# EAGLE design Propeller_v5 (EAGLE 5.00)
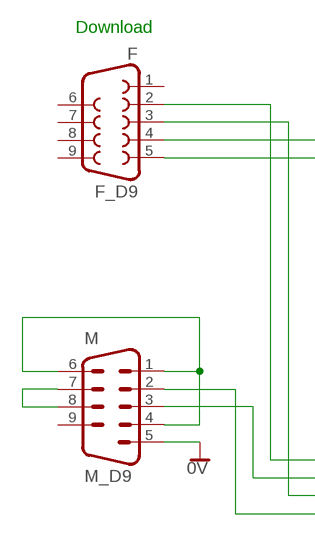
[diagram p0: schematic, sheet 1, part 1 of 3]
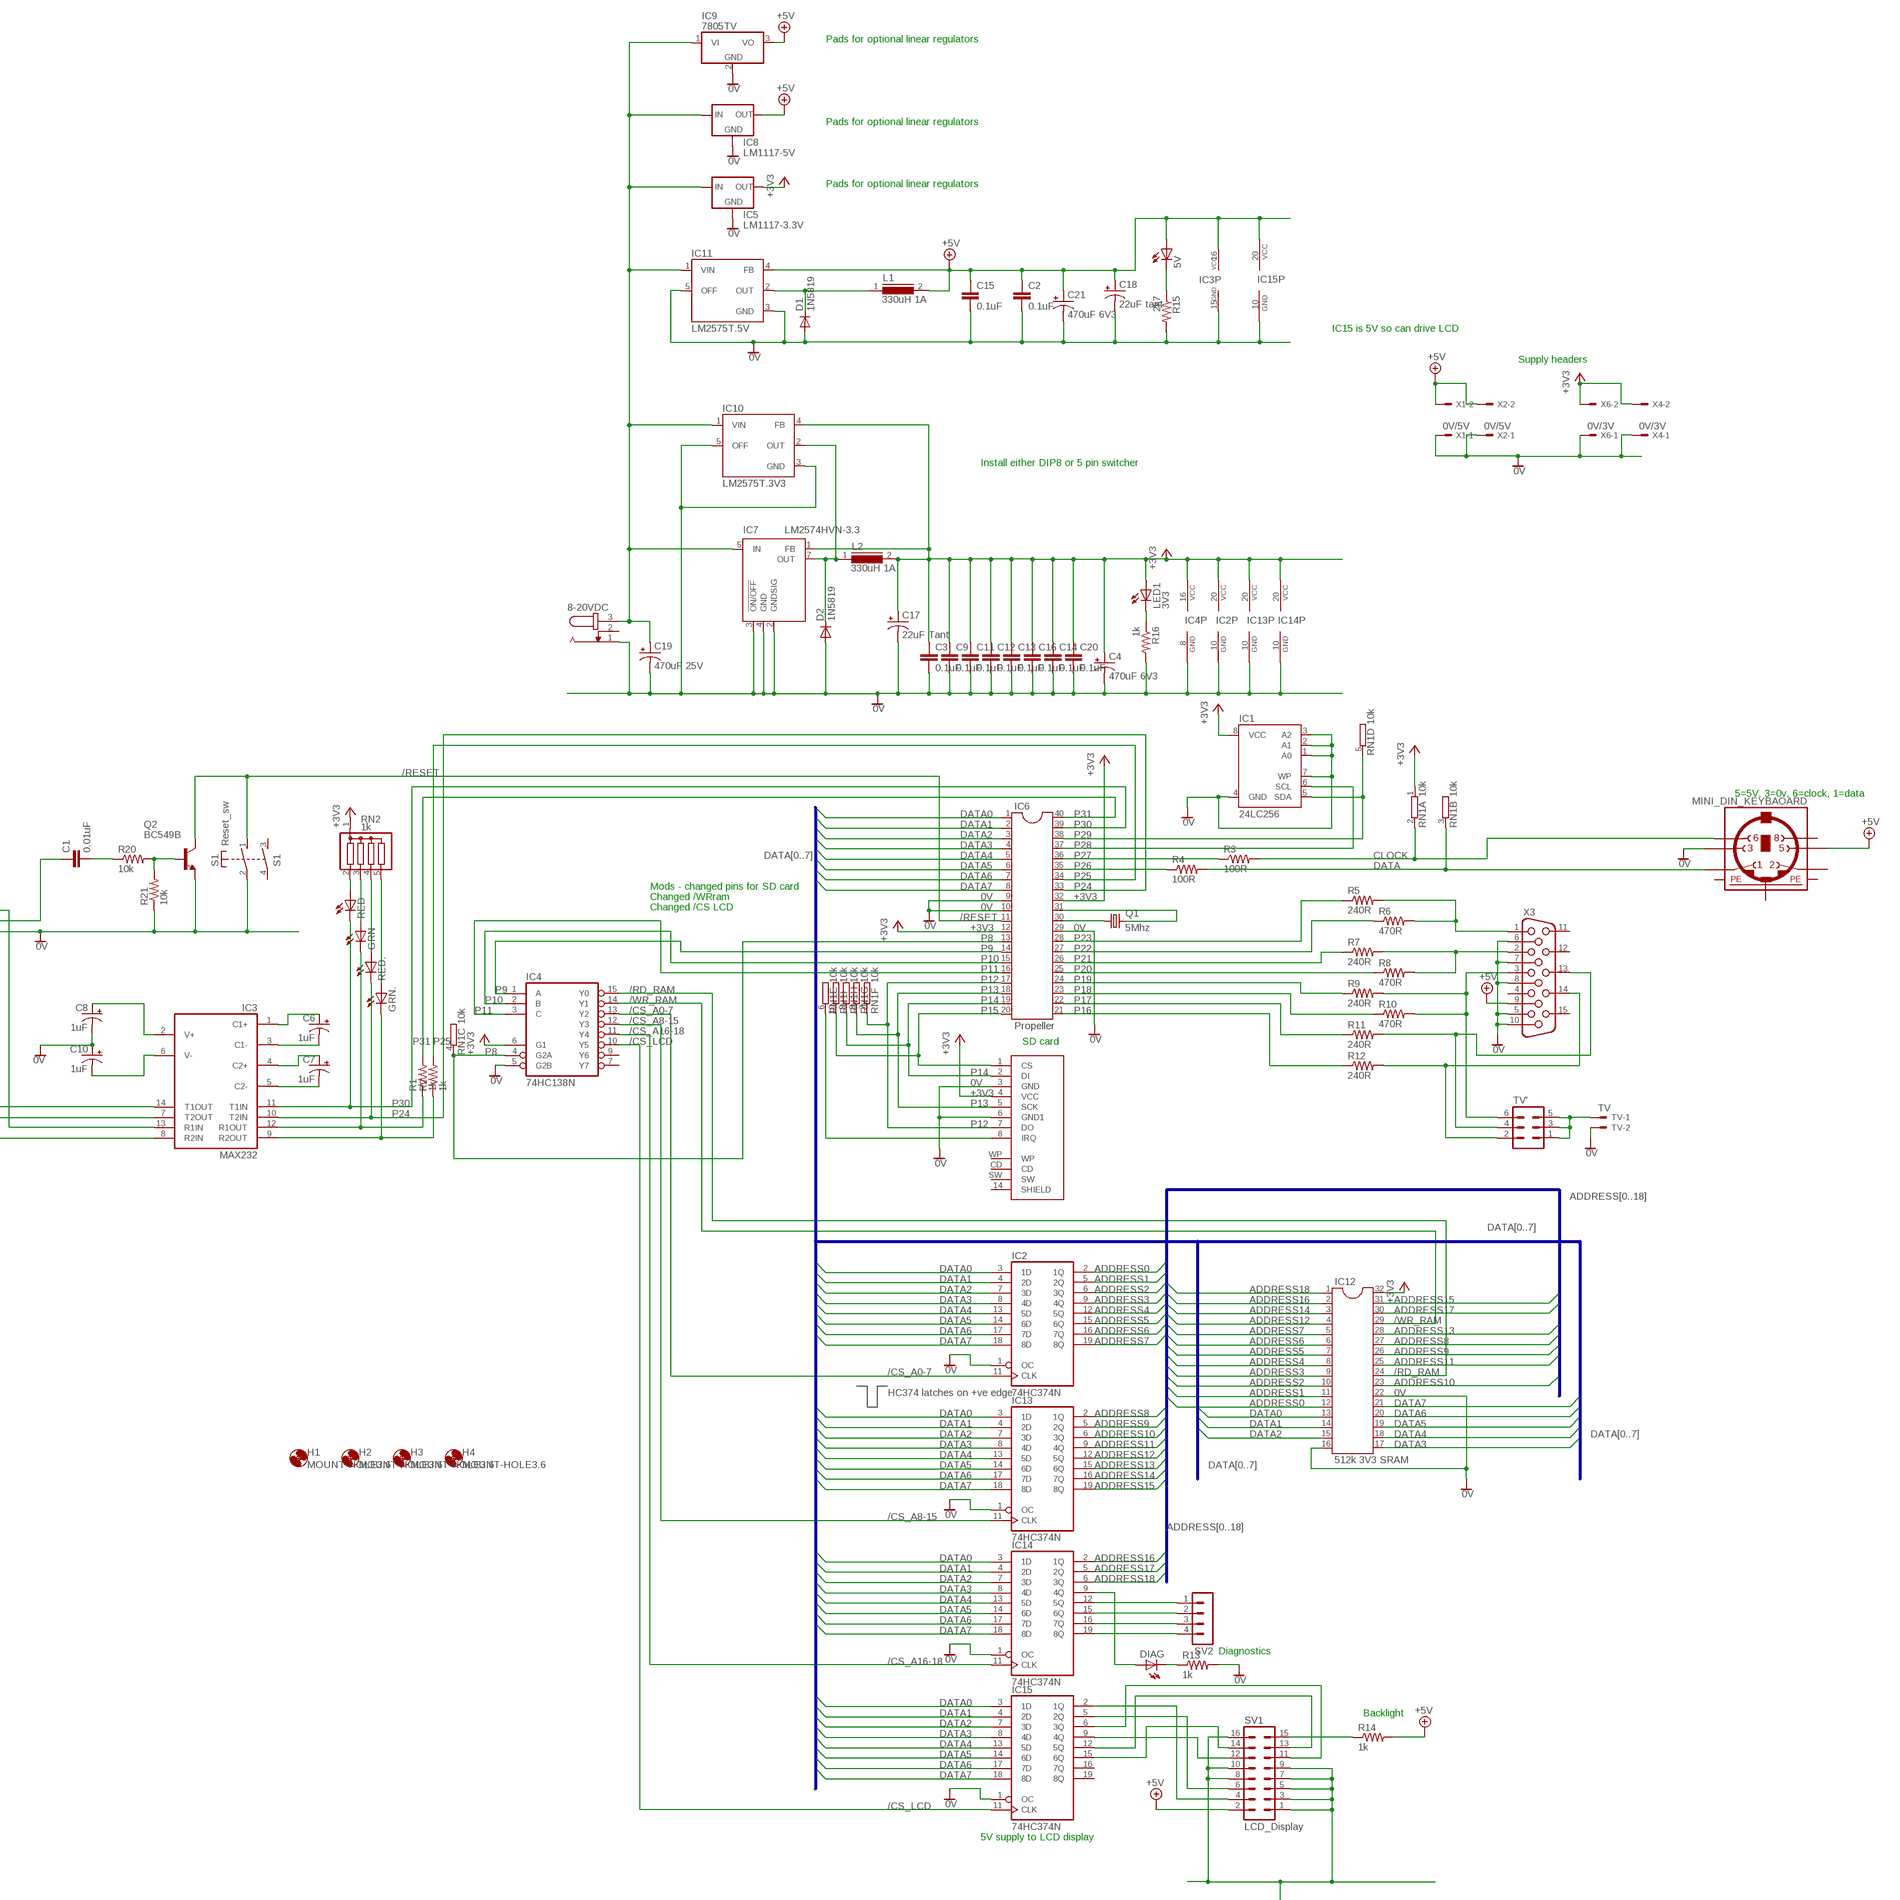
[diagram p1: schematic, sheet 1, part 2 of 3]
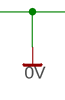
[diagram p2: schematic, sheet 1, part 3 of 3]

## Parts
5V  LED5MM  [LED5MM]
8-20VDC  JACK-PLUG0  [SPC4077]
C1  0.01uF  C-EU025-024X044  [C025-024X044]
C2  0.1uF  C-EU050-024X044  [C050-024X044]
C3  0.1uF  C-EU050-024X044  [C050-024X044]
C4  470uF 6V3  CPOL-USE5-8.5  [E5-8,5]
C6  1uF  CPOL-USE5-5  [E5-5]
C7  1uF  CPOL-USE5-5  [E5-5]
C8  1uF  CPOL-USE5-5  [E5-5]
C9  0.1uF  C-EU050-024X044  [C050-024X044]
C10  1uF  CPOL-USE5-5  [E5-5]
C11  0.1uF  C-EU050-024X044  [C050-024X044]
C12  0.1uF  C-EU050-024X044  [C050-024X044]
C13  0.1uF  C-EU050-024X044  [C050-024X044]
C14  0.1uF  C-EU050-024X044  [C050-024X044]
C15  0.1uF  C-EU050-024X044  [C050-024X044]
C16  0.1uF  C-EU050-024X044  [C050-024X044]
C17  22uF Tant  CPOL-USE5-5  [E5-5]
C18  22uF tant  CPOL-USE5-5  [E5-5]
C19  470uF 25V  CPOL-USE5-10.5  [E5-10,5]
C20  0.1uF  C-EU050-024X044  [C050-024X044]
C21  470uF 6V3  CPOL-USE5-8.5  [E5-8,5]
D1  1N5819  1N4004  [DO41-10]
D2  1N5819  1N4004  [DO41-10]
DIAG  LED5MM  [LED5MM]
F  F_D9  F09HP  [F09HP]
GRN  LED3MM  [LED3MM]
GRN.  LED3MM  [LED3MM]
H1  MOUNT-HOLE3.6  [3,6]
H2  MOUNT-HOLE3.6  [3,6]
H3  MOUNT-HOLE3.6  [3,6]
H4  MOUNT-HOLE3.6  [3,6]
IC1  24LC256  AT24CP  [DIL08]
IC2  74HC374N  74LS374N  [DIL20]
IC3  MAX232  [DIL16]
IC4  74HC138N  74LS138N  [DIL16]
IC5  LM1117-3.3V  LM1117V  [78XXS]
IC6  Propeller  DIL40  [DIL40]
IC7  LM2574HVN-3.3  [DIL08]
IC8  LM1117-5V  LM1117V  [78XXS]
IC9  7805TV  [TO220V]
IC10  LM2575T.3V3  LM2575T  [TO220-5]
IC11  LM2575T.5V  LM2575T  [TO220-5]
IC12  512k 3V3 SRAM  DIL32  [DIL32]
IC13  74HC374N  74LS374N  [DIL20]
IC14  74HC374N  74LS374N  [DIL20]
IC15  74HC374N  74LS374N  [DIL20]
L1  330uH 1A  82114R  [82114R]
L2  330uH 1A  82114R  [82114R]
LED1  3V3  LED5MM  [LED5MM]
M  M_D9  M09HP  [M09HP]
MINI_DIN_KEYBAOARD  MINI_DIN_6  [M_DIN6]
Q1  5Mhz  CRYSTALHC18U-V  [HC18U-V]
Q2  BC549B  [TO92-EBC]
R1  1k  R-US_0207/10  [0207/10]
R2  1k  R-US_0207/10  [0207/10]
R3  100R  R-US_0207/10  [0207/10]
R4  100R  R-US_0207/10  [0207/10]
R5  240R  R-US_0207/10  [0207/10]
R6  470R  R-US_0207/10  [0207/10]
R7  240R  R-US_0207/10  [0207/10]
R8  470R  R-US_0207/10  [0207/10]
R9  240R  R-US_0207/10  [0207/10]
R10  470R  R-US_0207/10  [0207/10]
R11  240R  R-US_0207/10  [0207/10]
R12  240R  R-US_0207/10  [0207/10]
R13  1k  R-US_0207/10  [0207/10]
R14  1k  R-US_0207/10  [0207/10]
R15  2k7  R-US_0207/10  [0207/10]
R16  1k  R-US_0207/10  [0207/10]
R20  10k  R-US_0207/10  [0207/10]
R21  10k  R-US_0207/10  [0207/10]
RED  LED3MM  [LED3MM]
RED.  LED3MM  [LED3MM]
RN1  10k  GE09R  [SIL10]
RN2  1k  G04R  [SIL5]
S1  Reset_sw  PVA1F  [PVA1F]
SV1  LCD_Display  MA08-2  [MA08-2]
SV2  MA04-1  [MA04-1]
TV  TV  22-23-2021  [22-23-2021]
TV'  MA03-2  [MA03-2]
U$1  SD_CARD_SOCKETSD  [SD-MMC_SOCKET-PP]
X1  0V/5V  22-23-2021  [22-23-2021]
X2  0V/5V  22-23-2021  [22-23-2021]
X3  HF15H  [HDF15H]
X4  0V/3V  22-23-2021  [22-23-2021]
X6  0V/3V  22-23-2021  [22-23-2021]

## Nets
0V [Gnd]: 8-20VDC.1 C2.2 C3.2 C4.- C8.- C9.2 C10.+ C11.2 C12.2 C13.2 C14.2 C15.2 C16.2 C17.- C18.- C19.- C20.2 C21.- D1.A D2.A F.5 IC1.1(A0) IC1.2(A1) IC1.3(A2) IC1.4(GND) IC1.7(WP) IC2.1(OC) IC2.10(GND) IC3.15(GND) IC4.5(G2B) IC4.8(GND) IC5.IN(GND) IC6.9 IC6.10 IC6.29 IC7.2(GNDSIG) IC7.3(!ON/OFF) IC7.4(GND) IC8.IN(GND) IC9.2(GND) IC10.3(GND) IC10.5(OFF) IC11.3(GND) IC11.5(OFF) IC12.16 IC12.22 IC13.1(OC) IC13.10(GND) IC14.1(OC) IC14.10(GND) IC15.1(OC) IC15.10(GND) M.5 MINI_DIN_KEYBAOARD.3 Q2.E R13.2 R15.2 R16.2 R21.1 S1.2(1:P) SV1.1 SV1.3 SV1.5 SV1.7 SV1.8 SV1.9 SV1.10 SV1.16 TV.2 U$1.3(GND) U$1.6(GND1) X1.1 X2.1 X3.5 X3.6 X3.7 X3.8 X3.10 X4.1 X6.1
+3V3 [3V]: C3.1 C4.+ C9.1 C11.1 C12.1 C13.1 C14.1 C16.1 C17.+ C20.1 IC1.8(VCC) IC2.20(VCC) IC4.6(G1) IC4.16(VCC) IC5.GND(OUT) IC6.12 IC6.32 IC7.1(FB) IC10.4(FB) IC12.32 IC13.20(VCC) IC14.20(VCC) L2.2 LED1.A RN1.1 RN2.1 U$1.4(VCC) X4.2 X6.2
+5V [5V]: 5V.A C2.1 C15.1 C18.+ C21.+ IC3.16(VCC) IC8.GND(OUT) IC9.3(VO) IC11.4(FB) IC15.20(VCC) L1.2 MINI_DIN_KEYBAOARD.5 R14.2 SV1.2 X1.2 X2.2 X3.9
/CS_A0-7: IC2.11(CLK) IC4.13(Y2)
/CS_A8-15: IC4.12(Y3) IC13.11(CLK)
/CS_A16-18: IC4.11(Y4) IC14.11(CLK)
/CS_LCD: IC4.10(Y5) IC15.11(CLK)
/RD_RAM: IC4.15(Y0) IC12.24
/RESET: IC6.11 Q2.C S1.1(1:S)
/WR_RAM: IC4.14(Y1) IC12.29
ADDRESS0: IC2.2(1Q) IC12.12
ADDRESS1: IC2.5(2Q) IC12.11
ADDRESS2: IC2.6(3Q) IC12.10
ADDRESS3: IC2.9(4Q) IC12.9
ADDRESS4: IC2.12(5Q) IC12.8
ADDRESS5: IC2.15(6Q) IC12.7
ADDRESS6: IC2.16(7Q) IC12.6
ADDRESS7: IC2.19(8Q) IC12.5
ADDRESS8: IC12.27 IC13.2(1Q)
ADDRESS9: IC12.26 IC13.5(2Q)
ADDRESS10: IC12.23 IC13.6(3Q)
ADDRESS11: IC12.25 IC13.9(4Q)
ADDRESS12: IC12.4 IC13.12(5Q)
ADDRESS13: IC12.28 IC13.15(6Q)
ADDRESS14: IC12.3 IC13.16(7Q)
ADDRESS15: IC12.31 IC13.19(8Q)
ADDRESS16: IC12.2 IC14.2(1Q)
ADDRESS17: IC12.30 IC14.5(2Q)
ADDRESS18: IC12.1 IC14.6(3Q)
CLOCK: MINI_DIN_KEYBAOARD.6 R3.2 RN1.2
DATA: MINI_DIN_KEYBAOARD.1 R4.2 RN1.3
DATA0: IC2.3(1D) IC6.1 IC12.13 IC13.3(1D) IC14.3(1D) IC15.3(1D)
DATA1: IC2.4(2D) IC6.2 IC12.14 IC13.4(2D) IC14.4(2D) IC15.4(2D)
DATA2: IC2.7(3D) IC6.3 IC12.15 IC13.7(3D) IC14.7(3D) IC15.7(3D)
DATA3: IC2.8(4D) IC6.4 IC12.17 IC13.8(4D) IC14.8(4D) IC15.8(4D)
DATA4: IC2.13(5D) IC6.5 IC12.18 IC13.13(5D) IC14.13(5D) IC15.13(5D)
DATA5: IC2.14(6D) IC6.6 IC12.19 IC13.14(6D) IC14.14(6D) IC15.14(6D)
DATA6: IC2.17(7D) IC6.7 IC12.20 IC13.17(7D) IC14.17(7D) IC15.17(7D)
DATA7: IC2.18(8D) IC6.8 IC12.21 IC13.18(8D) IC14.18(8D) IC15.18(8D)
N$1 [Fat]: 8-20VDC.3 C19.+ IC5.OUT(IN) IC7.5(IN) IC8.OUT(IN) IC9.1(VI) IC10.1(VIN) IC11.1(VIN)
N$2: GRN.K(C) IC3.12(R1OUT) R1.1
N$3: TV'.1 TV'.3 TV'.5 TV.1
N$4: IC6.30 Q1.1
N$5: DIAG.A IC14.9(4Q)
N$6: F.3 IC3.13(R1IN)
N$7: C1.1 F.4
N$8: Q2.B R20.2 R21.2
N$9: C1.2 R20.1
N$10: IC14.12(5Q) SV2.1
N$11: IC14.15(6Q) SV2.2
N$12: IC6.31 Q1.2
N$13: IC14.16(7Q) SV2.3
N$14: IC14.19(8Q) SV2.4
N$15: DIAG.K(C) R13.1
N$16 [Fat]: D1.C IC11.2(OUT) L1.1
N$17: R14.1 SV1.15
N$18: GRN..K(C) IC3.9(R2OUT) R2.1
N$19: R5.2 R6.2 X3.1
N$20: IC15.2(1Q) SV1.4
N$21: R7.2 R8.2 X3.2
N$22: IC15.5(2Q) SV1.6
N$23: IC15.6(3Q) SV1.11
N$24: IC15.9(4Q) SV1.12
N$25: R9.2 R10.2 TV'.6 X3.3
N$26: IC15.12(5Q) SV1.13
N$27: IC15.15(6Q) SV1.14
N$28: R11.2 TV'.4 X3.13
N$29: F.2 IC3.14(T1OUT)
N$30: R12.2 TV'.2 X3.14
N$32: 5V.K(C) R15.1
N$34: RED.A RN2.2
N$35 [Fat]: D2.C IC7.7(OUT) IC10.2(OUT) L2.1
N$36: C6.+ IC3.1(C1+)
N$37: C6.- IC3.3(C1-)
N$38: C7.+ IC3.4(C2+)
N$39: C7.- IC3.5(C2-)
N$40: C8.+ IC3.2(V+)
N$41: C10.- IC3.6(V-)
N$42: LED1.K(C) R16.1
N$43: GRN.A RN2.3
N$44: RED..A RN2.4
N$45: GRN..A RN2.5
N$46: RN1.6 U$1.8(IRQ)
N$49: M.1 M.4 M.6
N$51: M.7 M.8
N$57: IC3.7(T2OUT) M.3
N$61: IC3.8(R2IN) M.2
P8 [3V]: IC4.4(G2A) IC6.13 RN1.4
P9: IC4.1(A) IC6.14
P10: IC4.2(B) IC6.15
P11: IC4.3(C) IC6.16
P12: IC6.17 RN1.7 U$1.7(DO)
P13: IC6.18 RN1.8 U$1.5(SCK)
P14: IC6.19 RN1.9 U$1.2(DI)
P15: IC6.20 RN1.10 U$1.1(CS)
P16: IC6.21 R12.1
P17: IC6.22 R11.1
P18: IC6.23 R10.1
P19: IC6.24 R9.1
P20: IC6.25 R8.1
P21: IC6.26 R7.1
P22: IC6.27 R6.1
P23: IC6.28 R5.1
P24: IC3.10(T2IN) IC6.33 RED..K(C)
P25: IC6.34 R2.2
P26: IC6.35 R4.1
P27: IC6.36 R3.1
P28: IC1.6(SCL) IC6.37
P29: IC1.5(SDA) IC6.38 RN1.5
P30: IC3.11(T1IN) IC6.39 RED.K(C)
P31: IC6.40 R1.2
Unconnected: 8-20VDC.2 F.1 F.6 F.7 F.8 F.9 IC4.7(Y7) IC4.9(Y6) IC15.16(7Q) IC15.19(8Q) M.9 MINI_DIN_KEYBAOARD.2 MINI_DIN_KEYBAOARD.8 S1.3(2:S) S1.4(2:P) U$1.14(SHIELD) U$1.CD U$1.SW U$1.WP X3.4 X3.11 X3.12 X3.15

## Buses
DATA[0..7]
ADDRESS[0..18]

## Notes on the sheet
- Pads for optional linear regulators
- Pads for optional linear regulators
- Pads for optional linear regulators
- IC15 is 5V so can drive LCD
- Supply headers
- Install either DIP8 or 5 pin switcher
- 5=5V, 3=0v, 6=clock, 1=data
- Download
- Mods - changed pins for SD card
- Changed /WRram
- Changed /CS LCD
- SD card
- HC374 latches on +ve edge
- Diagnostics
- Backlight
- 5V supply to LCD display

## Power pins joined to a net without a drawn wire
PE1: MINI_DIN_KEYBAOARD.SH1(PE1)
PE2: MINI_DIN_KEYBAOARD.SH2(PE2)
PE3: MINI_DIN_KEYBAOARD.SH3(PE3)

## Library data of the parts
5V DIAG GRN GRN. LED1 RED RED. = led:LED: LED
8-20VDC = con-jack:JACK-PLUG: DC POWER JACK Power Jack, DC, Right Angle, Through Hole, Rated 5A at 16VDC, PC Terminals Distributor: Farnell (www.Farnell.de) Drawing: 84N1161.pdf / 84N1162.pdf Manufacturer: SPC Technology (www.spctechnology.com) Type: SPC4077 / SPC 4078
C1-C3 C9 C11-C16 C20 = rcl:C-EU: CAPACITOR, European symbol
C4 C6-C8 C10 C17-C19 C21 = rcl:CPOL-US: POLARIZED CAPACITOR, American symbol
D1 D2 = diode:1N4004: DIODE
F = con-subd:F09: SUB-D
H1-H4 = holes:MOUNT-HOLE: MOUNTING HOLE with drill center marker
IC1 = atmel:AT24C*: 2-wire serial EEPROM
IC2 IC13-IC15 = 74xx-us:74*374: Octal D type transparent LATCH, edge triggered
IC3 = maxim:MAX232: RS232 TRANSEIVER
IC4 = 74xx-us:74*138: 3-line to 8-line DECODER/DEMULTIPLEXER
IC5 IC8 = v-reg-3:LM1117
IC6 = ic-package:DIL40: Dual In Line
IC7 = linear:LM2574?-*: SIMPLE SWITCHER 0.5A Step-Down Voltage Regulator Source: http://cache.national.com/ds/LM/LM2574.pdf
IC9 = linear:78*: Positive VOLTAGE REGULATOR Source: http://cache.national.com/ds/LM/LM78L05.pdf http://www.fairchildsemi.com/ds/LM/LM7805.pdf
IC10 IC11 = v-reg-3:LM2575: National Semiconductor 1.0A "Simple Switcher"(c) 52kHz, Vout 1.23-37V (HV: 57V), Vin 40V (HV: 60V), 50µA standby current
IC12 = ic-package:DIL32: Dual In Line
L1 L2 = inductors:82114R: INDUCTOR
M = con-subd:M09: SUB-D
MINI_DIN_KEYBAOARD = mini_din:MINI_DIN_6
Q1 = crystal:CRYSTAL: CRYSTAL
Q2 = transistor-npn:BC549*: NPN Transistor
R1-R16 R20 R21 = rcl:R-US_: RESISTOR, American symbol
RN1 = resistor-sil:GE09R: SIL RESISTOR
RN2 = resistor-sil:G04R: SIL RESISTOR
S1 = switch-misc:PVA1: ITT SWITCH
SV1 = con-lstb:MA08-2: PIN HEADER
SV2 = con-lstb:MA04-1: PIN HEADER
TV X1 X2 X4 X6 = con-molex:22-23-2021: .100" (2.54mm) Center Header - 2 Pin
TV' = con-lstb:MA03-2: PIN HEADER
U$1 = SparkFunEagle-6-6-07:SD_CARD_SOCKET: SD/MMC Socket Media socket for SD and MMC cards. Push-push type. Schematic element and footprint production proven. Spark Fun Electronics SKU : PRT-00136
X3 = con-subd:HF15: SUB-D

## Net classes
1 5V: width 0.635 mm
2 3V: width 0.762 mm
3 Gnd: width 0.762 mm
4 Fat: width 1.27 mm

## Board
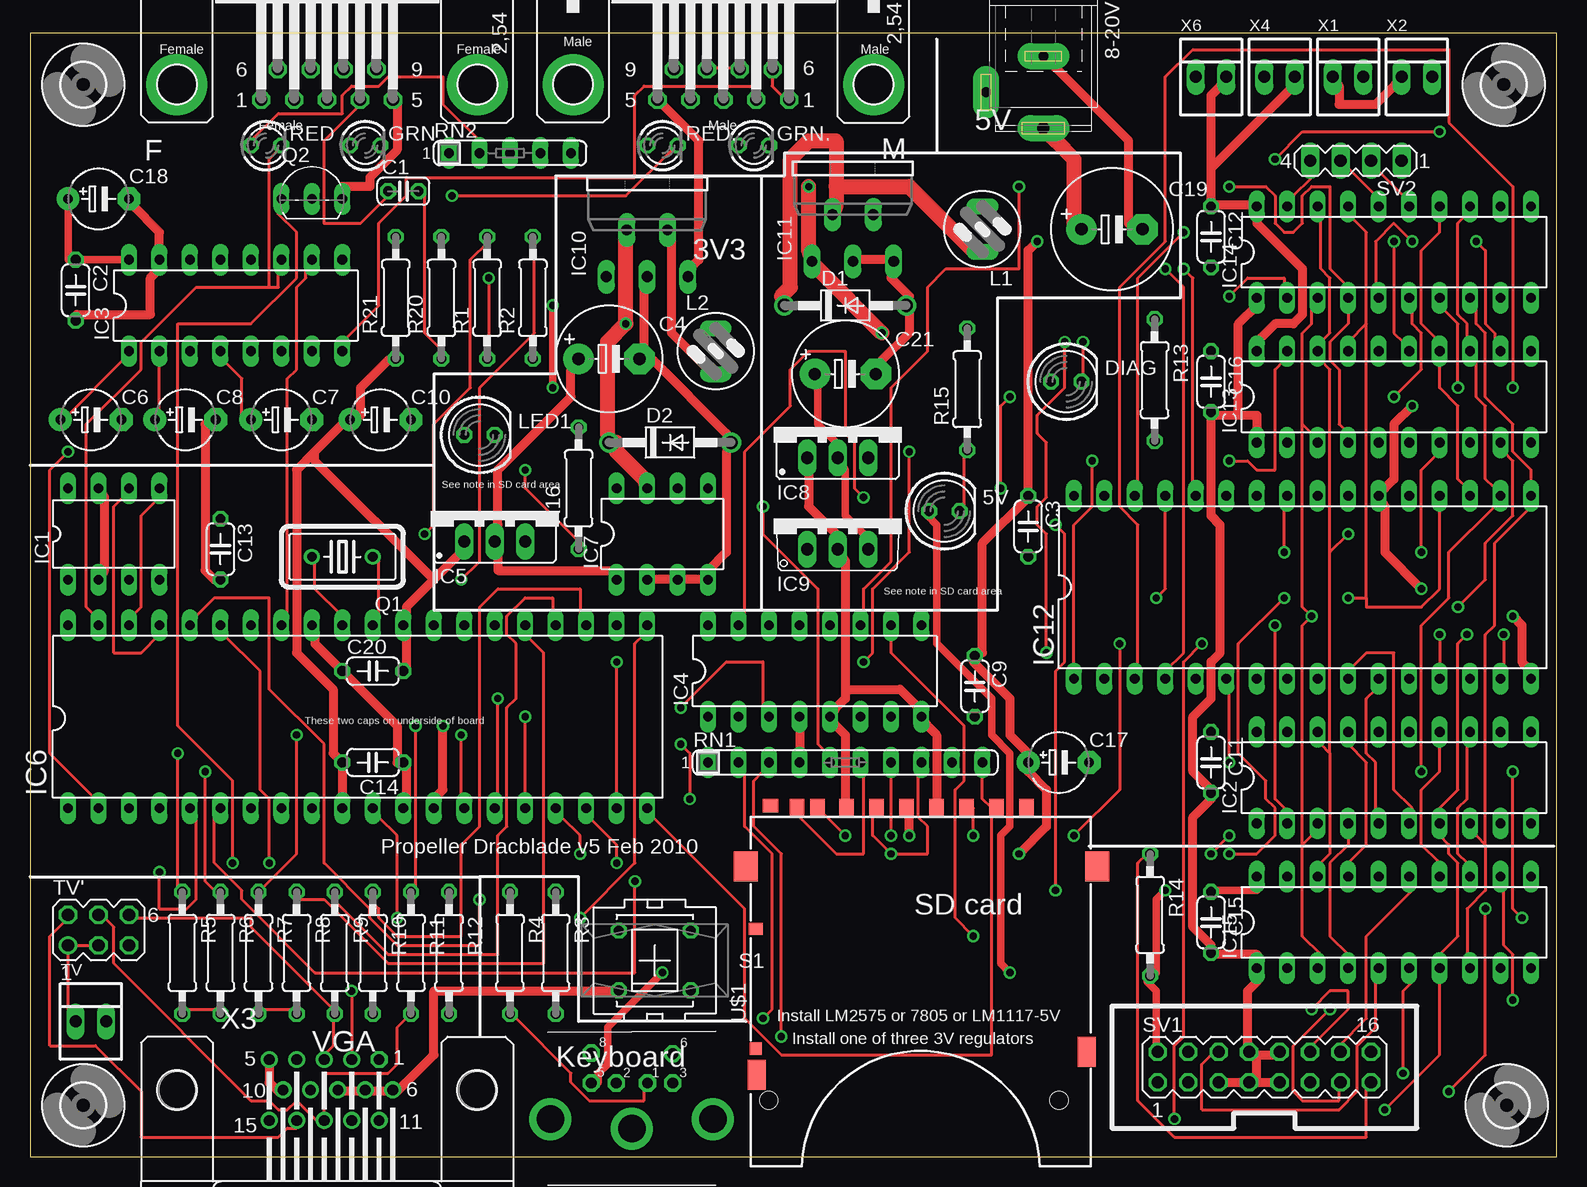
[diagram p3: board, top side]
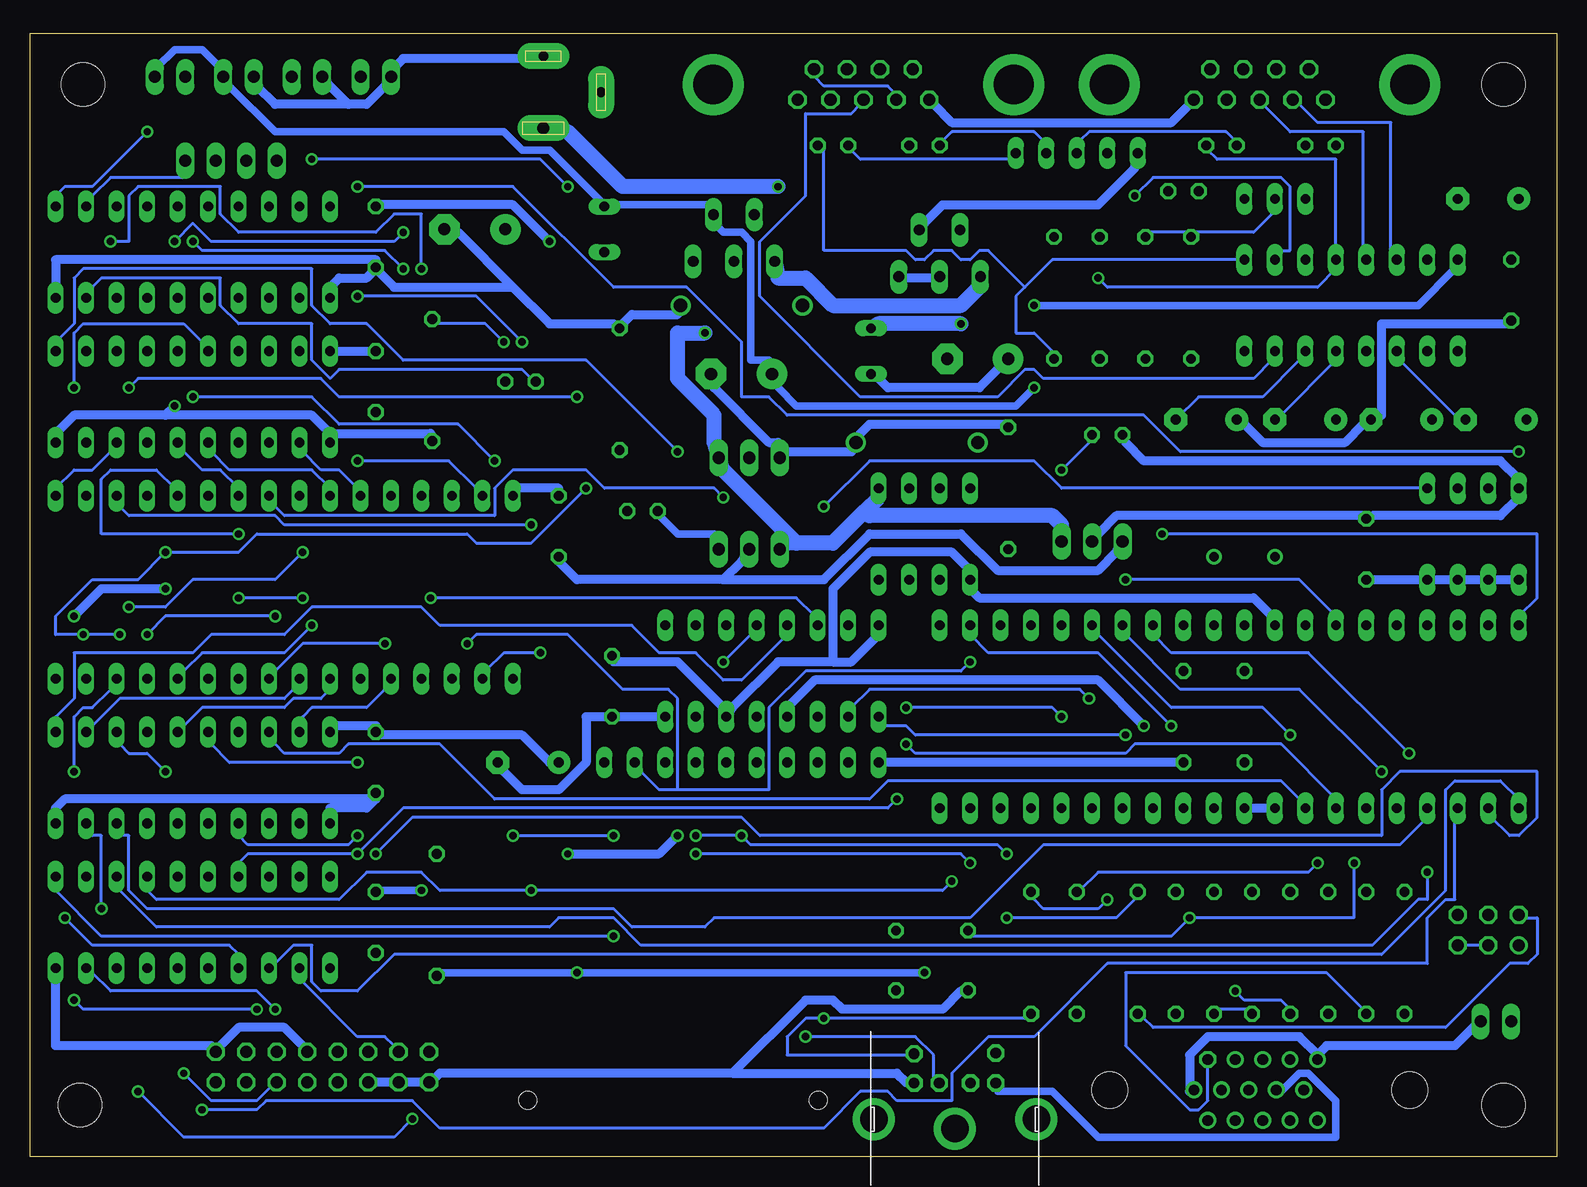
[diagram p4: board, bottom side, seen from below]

Size 127.23 x 93.65 mm. Coordinates in mm from the lower left corner, seen from the top.
Outline: 0,0 127.23,0 127.23,93.65 0,93.65 0,0
Copper layers (1*16): Top 0.035mm / dielectric 1.5mm / Bottom 0.035mm
Design rules "default *": minimum track width 10mil, minimum drill 24mil, track to track 8mil, track to pad 8mil, pad to pad 8mil, via to via 8mil, smd to smd 8mil, copper to edge 40mil, drill to drill 8mil, minimum pad ring 10mil, minimum via ring 8mil, stop-mask expansion 4mil, vias tented up to drill 0mil, thermal gap 10mil

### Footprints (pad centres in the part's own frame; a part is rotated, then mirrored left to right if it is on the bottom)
LED5MM = drill 0.813 octagon: A -1.27,0; K 1.27,0
SPC4077 = drill 0.8 pad 2.184 long: 1 -3,0; 2 0,-4.8 | drill 1 pad 2.184 long: 3 3,0
C025-024X044 = drill 0.813 octagon: 1 -1.27,0; 2 1.27,0
C050-024X044 = drill 0.813 octagon: 1 -2.54,0; 2 2.54,0
E5-8,5 = drill 1.016 pad 2.54 round: + -2.54,0 | drill 1.016 pad 2.54 octagon: - 2.54,0
E5-5 = drill 0.813 pad 1.905 round: + -2.54,0 | drill 0.813 pad 1.905 octagon: - 2.54,0
E5-10,5 = drill 1.016 pad 2.54 round: + -2.54,0 | drill 1.016 pad 2.54 octagon: - 2.54,0
DO41-10 = drill 1.118 round: A 5.08,0; C -5.08,0
F09HP = drill 1.016 octagon: 1 -5.486,-1.27; 2 -2.743,-1.27; 3 0,-1.27; 4 2.743,-1.27; 5 5.486,-1.27; 6 -4.115,1.27; 7 -1.372,1.27; 8 1.372,1.27; 9 4.115,1.27 | drill 3.302 pad 5.08 round: G1 -12.522,0; G2 12.522,0
LED3MM = drill 0.813 octagon: A -1.27,0; K 1.27,0
3,6 = hole 3.6: 0,0
DIL08 = drill 0.813 long: 1 -3.81,-3.81; 2 -1.27,-3.81; 3 1.27,-3.81; 4 3.81,-3.81; 5 3.81,3.81; 6 1.27,3.81; 7 -1.27,3.81; 8 -3.81,3.81
DIL20 = drill 0.813 long: 1 -11.43,-3.81; 2 -8.89,-3.81; 3 -6.35,-3.81; 4 -3.81,-3.81; 5 -1.27,-3.81; 6 1.27,-3.81; 7 3.81,-3.81; 8 6.35,-3.81; 9 8.89,-3.81; 10 11.43,-3.81; 11 11.43,3.81; 12 8.89,3.81; 13 6.35,3.81; 14 3.81,3.81; 15 1.27,3.81; 16 -1.27,3.81; 17 -3.81,3.81; 18 -6.35,3.81; 19 -8.89,3.81; 20 -11.43,3.81
DIL16 = drill 0.813 long: 1 -8.89,-3.81; 2 -6.35,-3.81; 3 -3.81,-3.81; 4 -1.27,-3.81; 5 1.27,-3.81; 6 3.81,-3.81; 7 6.35,-3.81; 8 8.89,-3.81; 9 8.89,3.81; 10 6.35,3.81; 11 3.81,3.81; 12 1.27,3.81; 13 -1.27,3.81; 14 -3.81,3.81; 15 -6.35,3.81; 16 -8.89,3.81
78XXS = drill 1.016 long: GND 0,-2.54; IN -2.54,-2.54; OUT 2.54,-2.54
DIL40 = drill 0.813 long: 1 -24.13,-7.62; 2 -21.59,-7.62; 3 -19.05,-7.62; 4 -16.51,-7.62; 5 -13.97,-7.62; 6 -11.43,-7.62; 7 -8.89,-7.62; 8 -6.35,-7.62; 9 -3.81,-7.62; 10 -1.27,-7.62; 11 1.27,-7.62; 12 3.81,-7.62; 13 6.35,-7.62; 14 8.89,-7.62; 15 11.43,-7.62; 16 13.97,-7.62; 17 16.51,-7.62; 18 19.05,-7.62; 19 21.59,-7.62; 20 24.13,-7.62; 21 24.13,7.62; 22 21.59,7.62; 23 19.05,7.62; 24 16.51,7.62; 25 13.97,7.62; 26 11.43,7.62; 27 8.89,7.62; 28 6.35,7.62; 29 3.81,7.62; 30 1.27,7.62; 31 -1.27,7.62; 32 -3.81,7.62; 33 -6.35,7.62; 34 -8.89,7.62; 35 -11.43,7.62; 36 -13.97,7.62; 37 -16.51,7.62; 38 -19.05,7.62; 39 -21.59,7.62; 40 -24.13,7.62
TO220V = drill 1.016 long: 1 -2.54,-2.54; 2 0,-2.54; 3 2.54,-2.54
TO220-5 = drill 0.9 long: 1 -3.4,-8.4; 2 -1.7,-4.5; 3 0,-8.4; 4 1.7,-4.5; 5 3.4,-8.4
DIL32 = drill 0.813 long: 1 -19.05,-7.62; 2 -16.51,-7.62; 3 -13.97,-7.62; 4 -11.43,-7.62; 5 -8.89,-7.62; 6 -6.35,-7.62; 7 -3.81,-7.62; 8 -1.27,-7.62; 9 1.27,-7.62; 10 3.81,-7.62; 11 6.35,-7.62; 12 8.89,-7.62; 13 11.43,-7.62; 14 13.97,-7.62; 15 16.51,-7.62; 16 19.05,-7.62; 17 19.05,7.62; 18 16.51,7.62; 19 13.97,7.62; 20 11.43,7.62; 21 8.89,7.62; 22 6.35,7.62; 23 3.81,7.62; 24 1.27,7.62; 25 -1.27,7.62; 26 -3.81,7.62; 27 -6.35,7.62; 28 -8.89,7.62; 29 -11.43,7.62; 30 -13.97,7.62; 31 -16.51,7.62; 32 -19.05,7.62
82114R = drill 0.813 long: 1 0,1.905; 2 0,-1.905
M09HP = drill 1.016 octagon: 1 -5.486,1.27; 2 -2.743,1.27; 3 0,1.27; 4 2.743,1.27; 5 5.486,1.27; 6 -4.115,-1.27; 7 -1.372,-1.27; 8 1.372,-1.27; 9 4.115,-1.27 | drill 3.302 pad 5.08 round: G1 -12.522,0; G2 12.522,0
M_DIN6 = drill 0.9 pad 1.422 octagon: 1 -1.3,-3.75; 2 1.3,-3.75; 3 -3.4,-3.75; 5 3.4,-3.75; 6 -3.4,-6.2; 8 3.4,-6.25 | drill 2.3 pad 3.5 round: SH1 6.8,-0.75; SH2 0,0.05; SH3 -6.75,-0.75
HC18U-V = drill 0.813 round: 1 -2.54,0; 2 2.54,0
TO92-EBC = drill 0.813 long: B 0,-1.27; C -2.54,-1.27; E 2.54,-1.27
0207/10 = drill 0.813 octagon: 1 -5.08,0; 2 5.08,0
SIL10 = drill 0.813 long: 1 -11.43,0; 2 -8.89,0; 3 -6.35,0; 4 -3.81,0; 5 -1.27,0; 6 1.27,0; 7 3.81,0; 8 6.35,0; 9 8.89,0; 10 11.43,0
SIL5 = drill 0.813 long: 1 -5.08,0; 2 -2.54,0; 3 0,0; 4 2.54,0; 5 5.08,0
PVA1F = drill 0.813 octagon: 1 -2.997,2.489; 2 -2.997,-2.489; 3 2.997,2.489; 4 2.997,-2.489
MA08-2 = drill 1.016 octagon: 1 -8.89,-1.27; 2 -8.89,1.27; 3 -6.35,-1.27; 4 -6.35,1.27; 5 -3.81,-1.27; 6 -3.81,1.27; 7 -1.27,-1.27; 8 -1.27,1.27; 9 1.27,-1.27; 10 1.27,1.27; 11 3.81,-1.27; 12 3.81,1.27; 13 6.35,-1.27; 14 6.35,1.27; 15 8.89,-1.27; 16 8.89,1.27
MA04-1 = drill 1.016 long: 1 -3.81,0; 2 -1.27,0; 3 1.27,0; 4 3.81,0
22-23-2021 = drill 1 long: 1 -1.27,0; 2 1.27,0
MA03-2 = drill 1.016 round: 1 -2.54,-1.27 | drill 1.016 octagon: 2 -2.54,1.27; 3 0,-1.27; 4 0,1.27; 5 2.54,-1.27; 6 2.54,1.27
SD-MMC_SOCKET-PP = smd 1.2 x 1.5: 1 6.88,29.85; 2 4.38,29.85; 3 1.88,29.85; 4 -0.62,29.85; 5 -3.12,29.85; 6 -5.62,29.85; 7 -8.04,29.85; 8 -9.728,29.87; 9 9.38,29.85 | smd 1.5 x 2.5: 12 -13.1,7.6; 13 14.402,9.525 | smd 2 x 2.5: 14 -14,25; 15 15.3,25 | smd 1 x 1.05: CD -13.18,9.8 | smd 1.3 x 1.1: SW -11.938,30.048 | smd 1.15 x 1: WP -13.18,19.8 | hole 1.5: -12.1,5.5; 12.1,5.5
HDF15H = drill 0.9 octagon: 1 4.329,2.54 | drill 0.9 round: 2 2.043,2.54; 3 -0.243,2.54; 4 -2.529,2.54; 5 -4.815,2.54; 6 5.472,0; 7 3.186,0; 8 0.9,0; 9 -1.386,0; 10 -3.672,0; 11 4.329,-2.54; 12 2.043,-2.54; 13 -0.243,-2.54; 14 -2.529,-2.54; 15 -4.815,-2.54 | hole 3: -12.5,0; 12.5,0

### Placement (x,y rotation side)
5V  76.19,53.81 0 top
8-20VDC  84.45,88.73 270 top
C1  31.11,80.48 0 top
C2  3.81,72.22 270 top
C3  83.18,52.54 270 top
C4  48.26,66.51 0 top
C6  5.08,61.43 0 top
C7  20.95,61.43 0 top
C8  12.95,61.43 0 top
C9  78.73,39.2 270 top
C10  29.2,61.43 0 top
C11  98.42,32.85 270 top
C12  98.42,76.67 270 top
C13  15.87,50.63 270 top
C14  28.57,32.85 180 top
C15  98.42,19.52 270 top
C16  98.42,64.61 270 top
C17  85.72,32.85 0 top
C18  5.71,79.84 0 top
C19  90.17,77.3 0 top
C20  28.57,40.47 0 top
C21  67.94,65.24 0 top
D1  67.94,70.95 0 top
D2  53.34,59.52 0 top
DIAG  86.36,64.61 0 top
F  24.76,89.37 0 top
GRN  27.93,84.29 0 top
GRN.  60.32,84.29 0 top
H1  4.44,4.28 0 top
H2  123.06,4.28 0 top
H3  4.44,89.37 0 top
H4  122.8,89.37 0 top
IC1  6.98,51.91 0 top
IC2  113.66,31.59 0 top
IC3  17.14,70.95 0 top
IC4  65.4,40.47 0 top
IC5  38.73,53.81 0 top
IC6  27.3,36.66 0 top
IC7  52.7,51.91 0 top
IC8  67.3,60.79 0 top
IC9  67.3,53.17 0 top
IC10  51.43,81.75 0 top
IC11  68.58,83.02 0 top
IC12  106.04,47.46 0 top
IC13  113.66,63.33 0 top
IC14  113.66,75.4 0 top
IC15  113.66,19.52 0 top
L1  79.37,77.3 180 top
L2  57.14,67.14 0 top
LED1  37.46,60.16 0 top
M  57.78,89.37 180 top
MINI_DIN_KEYBAOARD  50.16,2.38 180 top
Q1  26.03,50 180 top
Q2  23.49,81.11 0 top
R1  38.09,71.59 90 top
R2  41.91,71.59 90 top
R3  43.81,16.98 270 top
R4  40,16.98 270 top
R5  12.7,16.98 270 top
R6  15.87,16.98 270 top
R7  19.04,16.98 270 top
R8  22.22,16.98 270 top
R9  25.39,16.98 270 top
R10  28.57,16.98 270 top
R11  31.74,16.98 270 top
R12  34.92,16.98 270 top
R13  93.72,64.73 270 top
R14  93.34,20.16 270 top
R15  78.1,63.97 90 top
R16  45.71,55.71 90 top
R20  34.28,71.59 90 top
R21  30.47,71.59 90 top
RED  19.68,84.29 0 top
RED.  52.7,84.29 0 top
RN1  67.94,32.85 0 top
RN2  40,83.66 0 top
S1  52.06,16.35 0 top
SV1  102.86,7.46 0 top
SV2  110.48,83.02 180 top
TV  5.08,11.26 0 top
TV'  5.71,18.89 0 top
U$1  73.66,-0.8 0 top
X1  109.85,90 0 top
X2  115.56,90 0 top
X3  24.76,5.55 0 top
X4  104.14,90 0 top
X6  98.42,90 0 top

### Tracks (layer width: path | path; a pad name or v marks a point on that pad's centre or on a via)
0V  (via drill 0.61)
  Top 0.762: X3.10 20.7,5.42 19.93,6.19 19.93,7.71 X3.5 | X3.8 26.03,5.42 27.55,5.42 X3.7 28.32,5.42 29.84,5.42 X3.6 30.6,5.42 33.65,8.47 33.65,13.8 48.89,13.8 S1.2 | 102.23,6.19 SV1.9 | 102.23,8.47 103.75,8.47 SV1.10 | 102.23,6.19 102.23,8.47 | 102.23,6.19 SV1.7 SV1.5 | 102.23,8.47 SV1.8 101.47,9.23 101.47,13.8 102.23,14.57 IC15.1 102.23,16.85 98.42,16.85 C15.2 98.42,17.62 96.9,19.14 96.9,28.28 98.42,29.81 C11.2 98.42,30.57 96.9,32.09 96.9,36.66 98.42,38.19 98.42,41.24 99.18,42 99.18,52.67 98.42,53.43 98.42,61.81 | 100.71,61.81 102.23,61.81 IC13.1 | 98.42,61.81 100.71,61.81 | v115.18,62.57 113.66,61.05 113.66,56.48 112.9,55.71 IC12.22 112.9,54.19 112.9,50.38 v115.95,47.33 | v123.57,45.05 124.33,44.28 124.33,41.24 125.09,40.47 IC12.16 | 100.71,61.81 100.71,69.43 102.23,70.95 IC14.1 | X2.1 113.66,89.24 112.14,87.72 109.09,87.72 109.09,89.24 X1.1 | IC11.3 68.7,74.77 71.75,74.77 IC11.5 71.75,73.24 73.27,71.72 D1.A 73.27,70.19 73.27,68.67 70.99,66.38 C21.- | 8-20VDC.1 85.47,90.77 91.56,84.67 91.56,77.81 C19.- | IC1.7 6.22,54.95 6.22,48.86 IC1.2 | C2.2 3.93,70.19 10.03,70.19 10.03,73.24 10.79,74 IC3.15 10.79,77.05 8.5,79.34 C18.- | C13.2 15.36,48.09 14.6,48.86 14.6,61.05 C8.- | C20.2 31.36,40.47 31.36,43.52 IC6.29 31.36,45.05 31.36,45.81 33.65,48.09 | 33.65,48.09 35.94,50.38 IC5.IN | IC6.10 C14.2 25.27,33.62 25.27,38.95 22.22,42 22.22,57.24 23.74,58.76 | R21.1 29.84,66.38 27.55,64.1 27.55,61.81 C10.+ 26.03,61.05 23.74,58.76 | 33.65,48.09 23.74,58 23.74,58.76 | U$1.3 75.56,29.05 75.56,35.14 74.8,35.9 IC4.8 74.04,37.43 72.51,38.95 67.94,38.95 | U$1.6 67.94,29.05 67.94,35.14 67.18,35.9 IC4.5 67.18,37.43 67.94,38.19 67.94,38.95
  Top 0.762: 67.94,38.95 67.94,49.62 IC9.2 67.18,51.91 64.89,54.19 64.89,57.24 IC8.IN | IC7.2 IC7.3 IC7.4 56.51,48.86 58.03,50.38 58.03,58.76 D2.A 58.03,60.29 51.94,66.38 C4.- 51.18,67.14 51.18,72.48 IC10.3 | Q2.E 26.03,80.86 28.32,80.86 28.32,81.62 30.6,83.91 30.6,87.72 F.5 | M.5 52.7,87.72 55.75,84.67 55.75,74.77 54.99,74 IC10.5 | 98.42,61.81 C16.2
  Bottom 0.762: 19.93,8.47 19.17,9.23 8.5,9.23 6.98,10.76 TV.2 | 19.93,8.47 21.46,9.99 29.08,9.99 30.6,8.47 30.6,5.42 X3.6 | 19.93,8.47 X3.5 | 98.42,29.81 99.18,29.05 102.23,29.05 IC2.1 | 98.42,29.81 124.33,29.81 125.09,29.05 IC2.10 | C11.2 98.42,29.81 | IC15.10 125.09,9.23 112.14,9.23 SV1.16 111.37,9.23 109.85,10.76 106.04,10.76 104.52,9.23 SV1.10 | SV1.5 SV1.3 SV1.1 93.85,6.19 93.09,6.95 68.7,6.95 | 68.7,6.95 54.99,6.95 54.22,6.19 MINI_DIN_KEYBAOARD.3 | 68.7,6.95 62.61,13.04 60.32,13.04 59.56,12.28 51.18,12.28 49.65,13.8 S1.2 | 98.42,74 99.18,73.24 101.47,73.24 102.23,72.48 IC14.1 | IC14.10 125.09,74.77 98.42,74.77 C12.2 98.42,74 | 102.23,60.29 93.85,60.29 R13.2 | 115.95,61.81 v115.18,62.57 | 115.95,61.81 123.57,61.81 125.09,60.29 IC13.10 | v123.57,45.05 121.28,47.33 v115.95,47.33 | 102.23,60.29 103.75,61.81 115.95,61.81 | IC13.1 102.23,60.29 | 8-20VDC.1 86.23,91.53 96.13,91.53 96.9,90.77 X6.1 97.66,89.24 99.18,87.72 100.71,87.72 | 100.71,87.72 102.23,89.24 X4.1 | 100.71,87.72 106.8,87.72 108.33,89.24 X1.1 | D1.A 73.27,70.19 77.08,70.19 77.85,69.43 R15.2 78.61,69.43 83.94,69.43 86.99,72.48 | 86.99,72.48 91.56,77.05 C19.- | 98.42,74 96.9,72.48 86.99,72.48 | IC1.1 IC1.2 IC1.3 IC1.4 C13.2 | C2.2 3.93,69.43 14.6,69.43 14.6,61.81 C8.- 16.12,61.05 17.65,59.52 24.51,59.52 26.03,61.05 C10.+ | IC6.10 IC6.9 | IC4.8 C9.2 80.89,36.66 80.89,32.85 83.18,30.57 86.23,30.57 87.75,32.09 C17.- | 69.46,48.09 81.66,48.09 83.18,49.62 C3.2 | 69.46,48.09 67.94,49.62 IC9.2 | R16.2 45.84,61.05 57.27,61.05 58.03,60.29 D2.A 58.8,58.76 64.13,58.76 IC8.IN 64.89,59.52 65.65,59.52 70.23,64.1 C21.- | IC10.3 51.94,73.24 54.22,73.24 IC10.5
  Bottom 0.762: F.5 30.6,87.72 32.13,86.19 50.41,86.19 51.94,87.72 M.5 | 69.46,48.09 61.08,48.09 57.27,51.91 49.65,51.91 46.6,48.86 38.22,48.86 36.7,50.38 IC5.IN
+3V3  (via drill 0.61)
  Top 0.762: IC6.32 23.74,43.52 23.74,42.76 C20.1 30.6,35.9 30.6,32.85 C14.1 31.36,32.85 31.36,29.81 IC6.12 | L2.2 56.51,65.62 53.46,68.67 53.46,76.29 IC10.4 | IC7.1 48.89,48.86 38.98,48.86 38.98,50.38 IC5.GND 38.98,52.67 38.98,57.24 45.08,63.33 45.08,65.62 C4.+ | v73.27,26.76 73.27,29.05 U$1.4 | v82.42,25.24 84.7,27.52 84.7,30.57 83.18,32.09 C17.+ 83.18,33.62 81.66,35.14 81.66,38.19 78.61,41.24 C9.1 79.37,42 79.37,51.14 83.18,54.95 C3.1 83.18,75.53 v83.94,76.29 | 98.42,79.34 102.23,79.34 IC14.20 102.23,77.81 106.04,74 106.04,70.19 105.28,69.43 103.75,69.43 102.23,67.91 IC13.20 | 98.42,79.34 98.42,82.38 | 98.42,82.38 98.42,88.48 99.18,89.24 X6.2 | C12.1 98.42,79.34 | 98.42,82.38 105.28,89.24 X4.2
  Bottom 0.762: C14.1 RN1.1 | RN2.1 35.17,82.38 38.22,79.34 51.18,79.34 52.7,77.81 IC10.4 | C4.+ 48.13,64.1 55.75,64.1 56.51,64.86 L2.2 | LED1.A 35.94,59.52 34.41,58 4.69,58 3.17,56.48 IC1.8 3.17,54.95 4.69,53.43 15.36,53.43 C13.1 16.12,53.43 36.7,53.43 38.22,51.91 IC5.GND | IC6.32 23.74,45.05 25.27,46.57 48.13,46.57 48.89,47.33 IC7.1 48.89,48.86 50.41,50.38 57.27,50.38 60.32,47.33 60.32,41.24 | IC2.20 102.23,35.9 98.42,35.9 C11.1 98.42,35.14 86.23,35.14 83.94,32.85 C17.+ | v73.27,26.76 74.8,25.24 v82.42,25.24 | IC13.20 C16.1 | C3.1 83.18,55.71 86.99,55.71 IC12.32 | C9.1 78.61,41.24 73.27,41.24 69.46,37.43 IC4.6 68.7,37.43 64.89,41.24 60.32,41.24 | 60.32,41.24 58.8,41.24 56.51,43.52 IC4.16 | v83.94,76.29 86.99,79.34 98.42,79.34 C12.1
+5V  (via drill 0.61)
  Top 0.635: C15.1 98.42,22.19 102.23,22.19 IC15.20 | SV1.2 93.85,9.23 93.85,13.8 93.09,14.57 R14.2 93.85,15.33 93.85,21.43 v94.61,22.19 | v52.7,15.33 48.13,10.76 48.13,7.71 47.37,6.95 47.37,6.19 MINI_DIN_KEYBAOARD.5 | IC3.16 C2.1 3.17,74.77 C18.+ | C21.+ 65.65,64.1 65.65,61.05 67.18,59.52 IC8.GND 67.94,57.24 67.94,53.43 69.46,51.91 IC9.3 | v43.56,64.1 v43.56,70.95 | v81.66,15.33 80.89,16.09 80.89,26.76 81.66,27.52 81.66,33.62 80.13,35.14 80.13,38.19 75.56,42.76 75.56,52.67 74.8,53.43 5V.A
  Bottom 0.635: v94.61,22.19 98.42,22.19 C15.1 | X3.9 22.98,5.42 21.46,6.95 20.7,6.95 18.41,4.66 18.41,1.61 38.22,1.61 42.03,5.42 46.6,5.42 MINI_DIN_KEYBAOARD.5 | v52.7,15.33 v81.66,15.33 93.09,15.33 R14.2 | X2.2 116.71,90.77 115.18,92.29 112.9,92.29 111.37,90.77 X1.2 110.61,89.24 106.8,85.43 87.75,85.43 86.23,83.91 83.94,83.91 79.37,79.34 L1.2 78.61,79.34 70.23,79.34 IC11.4 70.23,77.81 69.46,77.05 67.94,77.05 67.18,76.29 67.18,66.38 65.65,66.38 C21.+ 64.89,64.1 63.37,62.57 45.08,62.57 v43.56,64.1 | 5V.A 74.8,53.43 73.27,51.91 70.23,51.91 IC9.3 | v43.56,70.95 11.55,70.95 8.5,74 IC3.16
/CS_A0-7
  Bottom 0.254: IC2.11 125.09,36.66 123.57,38.19 123.57,42 113.66,42 112.14,43.52 106.04,43.52 103.75,45.81 94.61,45.81 93.09,44.28 77.08,44.28 74.8,42 71.75,42 69.46,39.71 67.94,39.71 64.13,43.52 IC4.13
/CS_A8-15  (via drill 0.61)
  Top 0.254: v69.46,41.24 70.23,42 70.23,47.33 73.27,50.38 v73.27,58.76
  Bottom 0.254: v69.46,41.24 67.18,43.52 IC4.12 | v73.27,58.76 80.89,66.38 96.13,66.38 99.18,69.43 102.23,69.43 103.75,70.95 103.75,74 122.8,74 123.57,73.24 123.57,69.43 125.09,67.91 IC13.11
/CS_A16-18  (via drill 0.61)
  Top 0.254: v82.42,80.86 82.42,74 76.32,74 74.8,72.48 74.8,67.14 71.75,64.1 71.75,49.62 69.46,47.33 69.46,45.05 IC4.11 | v103.75,83.15 106.04,85.43 v117.47,85.43
  Bottom 0.254: v82.42,80.86 84.7,83.15 v103.75,83.15 | v117.47,85.43 122.04,80.86 124.33,80.86 125.09,80.1 IC14.11
/CS_LCD  (via drill 0.61)
  Top 0.254: v78.61,18.38 77.08,19.9 77.08,30.57 77.85,31.33 77.85,35.9 71.75,42 IC4.10
  Bottom 0.254: v78.61,18.38 121.28,18.38 125.09,22.19 IC15.11
/RD_RAM  (via drill 0.61)
  Top 0.254: v69.46,54.95 68.7,55.71 68.7,59.52 67.94,60.29 67.94,67.14 64.89,67.14 63.37,65.62 63.37,62.57 59.56,58.76 59.56,45.05 IC4.15
  Bottom 0.254: v69.46,54.95 70.23,55.71 79.37,55.71 80.89,57.24 86.99,57.24 88.51,55.71 88.51,53.43 106.04,53.43 106.8,54.19 IC12.24
/RESET  (via drill 0.61)
  Top 0.254: v30.6,19.9 30.6,26.76 29.08,28.28 IC6.11 | v16.89,24.47 16.89,31.33 12.31,35.9 12.31,69.43 18.41,69.43 22.22,73.24 22.22,77.05 20.7,78.58 Q2.C
  Bottom 0.254: S1.1 48.89,18.38 32.13,18.38 v30.6,19.9 16.89,19.9 v16.89,24.47
/WR_RAM  (via drill 0.61)
  Top 0.254: v93.85,46.57 94.61,47.33 IC12.29
  Bottom 0.254: v93.85,46.57 63.37,46.57 61.84,45.05 IC4.14
ADDRESS0  (via drill 0.61)
  Top 0.254: v103.75,44.28 103.75,29.81 104.52,29.05 IC2.2
  Bottom 0.254: v103.75,44.28 106.04,42 112.9,42 114.42,40.47 IC12.12
ADDRESS1
  Top 0.254: IC2.5 112.14,29.05 112.14,32.85 111.37,33.62 111.37,38.19 112.14,38.95 IC12.11
ADDRESS2
  Top 0.254: IC12.10 109.85,40.47 111.37,42 113.66,42 113.66,30.57 115.18,29.05 IC2.6
ADDRESS3  (via drill 0.61)
  Top 0.254: v97.66,42.76 96.13,41.24 96.13,9.99 95.37,9.23 v95.37,3.14 | v118.23,5.42 121.28,8.47 v121.28,20.66
  Bottom 0.254: v97.66,42.76 104.52,42.76 106.8,40.47 IC12.9 | v95.37,3.14 96.9,1.61 114.42,1.61 v118.23,5.42 | v121.28,20.66 121.28,26.76 122.04,26.76 IC2.9
ADDRESS4
  Bottom 0.254: IC12.8 105.28,38.95 106.04,38.19 119.76,38.19 IC2.12
ADDRESS5
  Bottom 0.254: IC12.7 102.23,38.95 102.99,38.19 105.28,38.19 106.04,37.43 112.9,37.43 IC2.15
ADDRESS6  (via drill 0.61)
  Top 0.254: v99.94,32.85 99.94,38.95 IC12.6
  Bottom 0.254: v99.94,32.85 110.61,32.85 112.14,34.38 IC2.16
ADDRESS7
  Bottom 0.254: IC12.5 97.66,38.95 99.18,37.43 103.75,37.43 104.52,36.66 IC2.19
ADDRESS8
  Bottom 0.254: IC12.27 99.94,55.71 101.47,57.24 102.99,57.24 104.52,58.76 IC13.2
ADDRESS9
  Bottom 0.254: IC12.26 102.23,55.71 103.75,57.24 110.61,57.24 112.14,58.76 IC13.5
ADDRESS10
  Bottom 0.254: IC12.23 109.85,55.71 111.37,57.24 112.9,57.24 114.42,58.76 IC13.6
ADDRESS11  (via drill 0.61)
  Top 0.254: v104.52,50.38 104.52,54.19 IC12.25 | v118.99,45.81 121.28,48.09 121.28,51.14 123.57,53.43 123.57,58 122.8,58.76 IC13.9
  Bottom 0.254: v104.52,50.38 106.8,48.09 113.66,48.09 115.95,45.81 v118.99,45.81
ADDRESS12  (via drill 0.61)
  Top 0.254: v94.61,74 96.13,72.48 96.13,42 94.61,40.47 IC12.4 | v120.52,76.29 121.28,75.53 121.28,69.43 122.04,68.67 122.04,67.91 IC13.12
  Bottom 0.254: v94.61,74 94.61,78.58 96.9,78.58 98.42,77.05 109.85,77.05 111.37,78.58 111.37,80.86 118.23,80.86 118.99,80.1 118.99,76.29 v120.52,76.29
ADDRESS13  (via drill 0.61)
  Top 0.254: v96.13,74 96.9,73.24 96.9,55.71 IC12.28 | v113.66,76.29 113.66,68.67 114.42,67.91 IC13.15
  Bottom 0.254: v96.13,74 97.66,75.53 112.9,75.53 v113.66,76.29
ADDRESS14  (via drill 0.61)
  Top 0.254: v123.57,64.1 123.57,80.86 118.23,86.19 118.23,92.29 96.9,92.29 94.61,90 94.61,76.29 90.8,72.48 90.8,54.19 92.32,52.67 92.32,40.47 IC12.3
  Bottom 0.254: v123.57,64.1 123.57,68.67 122.8,69.43 114.42,69.43 112.9,67.91 IC13.16
ADDRESS15  (via drill 0.61)
  Top 0.254: v99.94,58 101.47,58 102.23,57.24 103.75,57.24 103.75,65.62 104.52,66.38 IC13.19
  Bottom 0.254: v99.94,58 92.32,58 90.04,55.71 IC12.31
ADDRESS16  (via drill 0.61)
  Top 0.254: v84.7,42 84.7,51.91 83.94,52.67 83.94,54.19 84.7,54.95 84.7,59.52 83.94,60.29 83.94,61.81 86.23,64.1 v86.23,67.91 | v99.94,71.72 101.47,73.24 104.52,73.24 104.52,72.48 IC14.2
  Bottom 0.254: v84.7,42 87.75,42 89.28,40.47 IC12.2 | v86.23,67.91 90.04,71.72 v99.94,71.72
ADDRESS17  (via drill 0.61)
  Top 0.254: v96.13,77.05 92.32,73.24 92.32,55.71 IC12.30 | v115.18,76.29 113.66,77.81 112.14,76.29 112.14,72.48 IC14.5
  Bottom 0.254: v96.13,77.05 96.9,76.29 112.14,76.29 113.66,77.81 v115.18,76.29
ADDRESS18  (via drill 0.61)
  Top 0.254: v88.51,58 88.51,54.19 86.99,52.67 IC12.1 | v113.66,63.33 115.95,65.62 115.95,68.67 115.18,69.43 115.18,70.95 IC14.6
  Bottom 0.254: v88.51,58 91.56,61.05 101.47,61.05 103.75,63.33 v113.66,63.33
CLOCK  (via drill 0.61)
  Top 0.254: v61.08,11.52 61.84,12.28 61.84,25.24 59.56,27.52 59.56,32.09 RN1.2
  Bottom 0.254: R3.2 44.32,11.52 v61.08,11.52 62.61,11.52 64.13,9.99 64.13,8.47 54.22,8.47 MINI_DIN_KEYBAOARD.6
DATA  (via drill 0.61)
  Top 0.254: R4.2 40.51,11.52 45.08,6.95 45.08,6.19 46.6,4.66 51.18,4.66 51.18,5.42 MINI_DIN_KEYBAOARD.1 | v62.61,9.99 62.61,25.24 60.32,27.52 60.32,31.33 61.08,32.09 RN1.3
  Bottom 0.254: v62.61,9.99 53.46,9.99 51.94,8.47 51.94,6.19 MINI_DIN_KEYBAOARD.1
DATA0  (via drill 0.61)
  Top 0.254: 106.04,61.05 106.8,60.29 IC13.3 | 106.04,61.05 106.04,68.67 106.8,69.43 106.8,70.95 IC14.3 | 106.04,61.05 106.04,45.81 v106.8,45.05 106.04,44.28 106.04,26 | v117.47,43.52 IC12.13 | 106.04,26 106.04,18.38 107.56,16.85 IC15.3 | 106.04,26 106.8,26.76 IC2.3
  Bottom 0.254: v117.47,43.52 115.95,45.05 v106.8,45.05 | IC6.1 3.17,29.81 4.69,31.33 8.5,31.33 9.27,30.57 9.27,22.19 14.6,16.85 96.9,16.85 99.94,13.8 102.99,13.8 103.75,14.57 103.75,17.62 105.28,17.62 106.8,16.09 IC15.3
DATA1  (via drill 0.61)
  Top 0.254: IC13.4 109.85,60.29 109.09,61.05 109.09,65.62 108.33,66.38 108.33,67.91 109.85,69.43 IC14.4 109.85,72.48 108.33,74 108.33,80.86 106.8,80.86 106.04,80.1 106.04,77.81 105.28,77.05 104.52,77.05 103.75,77.81 103.75,80.1 102.99,80.86 v99.94,80.86 | v98.42,25.24 v99.94,26.76 | IC15.4 109.85,16.85 108.33,18.38 108.33,24.47 109.85,26 IC2.4 | v123.57,32.09 123.57,20.66 v124.33,19.9 | v3.17,58.76 1.65,57.24 1.65,33.62 5.46,29.81 IC6.2
  Bottom 0.254: v98.42,25.24 95.37,28.28 67.94,28.28 66.42,26.76 14.6,26.76 14.6,30.57 13.08,32.09 1.65,32.09 1.65,28.28 3.17,26.76 3.93,26.76 5.46,28.28 IC6.2 | v99.94,26.76 100.71,26 109.09,26 109.85,26.76 IC2.4 | v123.57,32.09 123.57,36.66 122.8,37.43 122.04,37.43 120.52,38.95 IC12.14 | v124.33,19.9 122.04,17.62 110.61,17.62 109.85,16.85 IC15.4 | v99.94,80.86 86.99,80.86 78.61,72.48 72.51,72.48 67.94,67.91 67.94,63.33 65.65,63.33 64.13,61.81 34.41,61.81 31.36,58.76 v3.17,58.76
DATA2  (via drill 0.61)
  Top 0.254: v112.9,3.9 117.47,8.47 IC15.7 117.47,16.85 118.99,18.38 118.99,24.47 118.23,25.24 118.23,26 117.47,26.76 IC2.7 117.47,29.05 118.99,30.57 118.99,42.76 v119.76,43.52 | v122.8,43.52 122.8,40.47 IC12.15 | v115.95,50.38 115.95,57.24 117.47,58.76 IC13.7 | v118.99,64.1 118.99,69.43 117.47,70.95 IC14.7 | v81.66,63.33 80.89,62.57 v80.89,55.71
  Bottom 0.254: v112.9,3.9 108.33,3.9 107.56,4.66 95.37,4.66 93.09,2.38 61.08,2.38 58.03,5.42 55.75,5.42 54.99,4.66 50.41,4.66 50.41,6.95 47.37,9.99 43.56,9.99 37.46,16.09 10.79,16.09 10.79,19.9 9.27,21.43 8.5,21.43 8.5,28.28 IC6.3 | v119.76,43.52 v122.8,43.52 125.09,43.52 125.09,45.05 122.04,48.09 118.23,48.09 v115.95,50.38 109.85,50.38 108.33,51.91 90.8,51.91 90.04,51.14 85.47,51.14 v80.89,55.71 | v118.99,64.1 118.23,64.86 102.99,64.86 101.47,63.33 v81.66,63.33
DATA3
  Top 0.254: IC14.8 120.52,70.95 120.52,69.43 121.28,68.67 121.28,63.33 123.57,61.05 123.57,58.76 125.09,57.24 IC12.17 125.09,54.19 122.04,51.14 122.04,44.28 121.28,43.52 121.28,26 | 121.28,26 121.28,22.19 119.76,20.66 119.76,16.85 IC15.8 | 121.28,26 120.52,26.76 IC2.8
  Bottom 0.254: IC13.8 120.52,58.76 122.04,57.24 123.57,57.24 125.09,55.71 IC12.17 | IC6.4 10.79,28.28 13.08,26 42.79,26 48.89,19.9 70.23,19.9 70.99,19.14 77.08,19.14 78.61,20.66 117.47,20.66 118.99,22.19 118.99,26.76 119.76,26.76 IC2.8
DATA4  (via drill 0.61)
  Top 0.254: IC14.13 119.76,78.58 118.99,77.81 118.99,70.19 119.76,69.43 119.76,67.91 IC13.13 120.52,66.38 120.52,63.33 121.28,62.57 121.28,56.48 122.04,55.71 IC12.18 122.04,54.19 118.23,50.38 118.23,46.57 115.95,44.28 v115.95,32.09 | v10.79,23.71 10.79,20.66 13.08,20.66 13.84,21.43 13.84,28.28 IC6.5 | IC2.13 119.76,34.38 119.76,29.81 118.99,29.05 118.99,25.24 119.76,24.47 IC15.13
  Bottom 0.254: v10.79,23.71 10.79,21.43 11.55,21.43 15.36,17.62 76.32,17.62 78.61,19.9 83.18,19.9 83.94,19.14 116.71,19.14 119.76,22.19 IC15.13 | v115.95,32.09 117.47,33.62 118.99,33.62 119.76,34.38 IC2.13
DATA5  (via drill 0.61)
  Top 0.254: IC14.14 117.47,77.05 115.95,75.53 115.95,69.43 117.47,67.91 IC13.14 117.47,64.1 118.99,62.57 118.99,56.48 119.76,55.71 IC12.19 | v50.41,22.95 50.41,15.33 23.74,15.33 17.65,21.43 17.65,22.19 15.36,24.47 15.36,28.28 IC6.6 | IC2.14 117.47,32.09 115.95,30.57 115.95,26 117.47,24.47 IC15.14 | v85.47,52.67 86.23,51.91 86.23,41.24 85.47,40.47 v85.47,22.19
  Bottom 0.254: v50.41,22.95 51.18,22.19 v85.47,22.19 93.09,22.19 94.61,23.71 99.18,23.71 101.47,21.43 116.71,21.43 117.47,22.19 IC15.14 | v85.47,52.67 106.04,52.67 106.8,53.43 118.99,53.43 119.76,54.19 IC12.19
DATA6  (via drill 0.61)
  Top 0.254: 111.37,69.43 109.85,67.91 IC13.17 | 111.37,69.43 111.37,77.05 109.85,78.58 IC14.17 | 111.37,46.57 111.37,69.43 | 111.37,46.57 111.37,45.81 115.95,45.81 117.47,47.33 IC12.20 | v54.22,34.38 54.99,33.62 v54.99,29.81 | IC2.17 109.85,34.38 111.37,32.85 111.37,26 109.85,24.47 IC15.17 | v109.85,46.57 111.37,46.57 | v104.52,46.57 100.71,42.76 100.71,33.62 102.99,31.33 102.99,29.81 103.75,29.05 103.75,26.76 102.23,25.24 v99.94,25.24
  Bottom 0.254: v54.22,34.38 53.46,33.62 35.94,33.62 35.17,34.38 22.98,34.38 18.41,29.81 IC6.7 | v54.99,29.81 55.75,29.05 96.13,29.05 v99.94,25.24 109.09,25.24 109.85,24.47 IC15.17 | v104.52,46.57 v109.85,46.57
DATA7  (via drill 0.61)
  Top 0.254: IC14.18 107.56,78.58 107.56,74 108.33,73.24 108.33,68.67 107.56,67.91 IC13.18 107.56,66.38 108.33,65.62 108.33,50.38 | 108.33,33.62 108.33,25.24 107.56,24.47 IC15.18 | 108.33,33.62 107.56,34.38 IC2.18 | 108.33,50.38 v109.85,51.91 | 108.33,33.62 108.33,50.38
  Bottom 0.254: IC6.8 21.46,29.81 22.98,31.33 55.75,31.33 57.27,29.81 88.51,29.81 93.09,34.38 100.71,34.38 101.47,33.62 106.04,33.62 106.8,34.38 IC2.18 | v109.85,51.91 121.28,51.91 121.28,56.48 120.52,57.24 116.71,57.24 115.18,55.71 IC12.21
N$1  (via drill 0.61)
  Top 1.27: 8-20VDC.3 85.47,84.67 86.99,83.15 86.99,77.81 C19.+ | v64.89,80.86 64.89,75.53 IC11.1 65.65,74 v70.99,68.67
  Bottom 1.27: 57.65,53.81 60.32,51.14 63.37,51.14 | 57.65,53.81 56.51,54.95 IC7.5 | 63.37,51.14 64.13,51.14 IC9.1 | IC5.OUT 41.27,52.67 42.03,53.43 57.27,53.43 57.65,53.81 | 63.37,51.14 69.46,57.24 IC8.OUT 70.23,59.52 70.23,61.81 73.27,64.86 73.27,68.67 v70.99,68.67 | IC10.1 48.13,72.48 49.65,70.95 60.32,70.95 62.61,73.24 64.89,73.24 IC11.1 | v64.89,80.86 77.85,80.86 82.42,85.43 8-20VDC.3
N$2  (via drill 0.61)
  Top 0.254: v38.22,73.24 38.22,67.14 R1.1
  Bottom 0.254: GRN.K 29.08,83.91 28.32,83.15 18.41,83.15 IC3.12 18.41,74 19.93,72.48 37.46,72.48 v38.22,73.24
N$3
  Top 0.254: TV.1 3.17,12.28 TV'.1 TV'.3
  Bottom 0.254: TV'.3 TV'.5
N$4
  Top 0.254: IC6.30 29.08,45.05 29.08,49.62 Q1.1
N$5
  Bottom 0.254: DIAG.A 85.47,64.86 86.23,65.62 101.47,65.62 102.23,64.86 103.75,66.38 103.75,69.43 109.85,69.43 111.37,70.95 111.37,73.24 121.28,73.24 122.04,72.48 IC14.9
N$6
  Bottom 0.254: IC3.13 16.12,75.53 16.12,85.43 22.22,85.43 24.51,87.72 F.3
N$7
  Top 0.254: C1.1 29.84,80.1 27.55,77.81 24.51,77.81 24.51,84.67 27.55,87.72 F.4
N$8
  Bottom 0.254: 30.6,77.05 34.41,77.05 R20.2 | 30.6,77.05 25.27,77.05 23.74,78.58 Q2.B | 30.6,77.05 R21.2
N$9
  Top 0.254: R20.1 34.41,67.14 32.89,68.67 32.89,80.1 C1.2
N$10
  Bottom 0.254: IC14.12 122.04,80.1 120.52,81.62 114.42,81.62 SV2.1
N$11
  Top 0.254: IC14.15 114.42,80.1 112.14,82.38 SV2.2
N$12
  Top 0.254: IC6.31 26.03,45.05 23.74,47.33 23.74,49.62 Q1.2
N$13
  Top 0.254: IC14.16 112.14,80.1 SV2.3
N$14
  Top 0.254: IC14.19 105.28,80.1 106.8,81.62 SV2.4
N$15  (via drill 0.61)
  Top 0.254: v87.75,67.91 87.75,64.86 DIAG.K
  Bottom 0.254: v87.75,67.91 89.28,69.43 93.85,69.43 R13.1
N$16
  Top 1.27: 67.18,80.86 73.27,80.86 78.61,75.53 L1.1 | 67.18,80.86 67.18,79.34 IC11.2 | 67.18,80.86 67.18,84.67 64.89,84.67 63.37,83.15 63.37,72.48 62.61,71.72 D1.C
N$17
  Top 0.254: R14.1 93.09,25.24 92.32,24.47 92.32,4.66 95.37,1.61 111.37,1.61 111.37,6.19 SV1.15
N$18
  Bottom 0.254: IC3.9 42.03,74.77 44.32,72.48 | 44.32,72.48 45.08,71.72 45.08,68.67 43.56,68.67 42.03,67.14 R2.1 | 44.32,72.48 47.37,75.53 48.13,75.53 48.89,74.77 49.65,74.77 50.41,75.53 51.94,75.53 52.7,74.77 53.46,74.77 54.22,75.53 61.08,75.53 61.08,83.91 GRN..K
N$19
  Top 0.254: R5.2 13.08,12.28 15.36,12.28 R6.2
  Bottom 0.254: X3.1 29.08,7.71 29.08,4.66 29.84,3.9 30.6,3.9 35.94,9.23 35.94,15.33 19.17,15.33 16.12,12.28 R6.2
N$20
  Bottom 0.254: IC15.2 104.52,14.57 99.94,9.99 97.66,9.99 96.9,9.23 SV1.4
N$21  (via drill 0.61)
  Top 0.254: R7.2 19.17,12.28 22.22,12.28 R8.2 | v26.79,13.8 26.79,8.47 X3.2
  Bottom 0.254: v26.79,13.8 26.03,13.04 22.98,13.04 22.22,12.28 R8.2
N$22
  Top 0.254: IC15.5 112.14,14.57 112.14,10.76 110.61,9.23 110.61,5.42 109.09,3.9 97.66,3.9 97.66,7.71 98.42,8.47 SV1.6
N$23  (via drill 0.61)
  Top 0.254: v114.42,6.95 114.42,13.8 115.18,14.57 IC15.6
  Bottom 0.254: v114.42,6.95 112.14,4.66 108.33,4.66 106.8,6.19 SV1.11
N$24  (via drill 0.61)
  Top 0.254: v106.8,12.28 108.33,13.8 109.85,13.8 109.85,12.28 106.8,9.23 SV1.12
  Bottom 0.254: v106.8,12.28 108.33,13.8 120.52,13.8 122.04,15.33 IC15.9
N$25
  Top 0.254: X3.3 24.51,8.47 25.27,9.23 25.27,11.52 R9.2 25.27,12.28 18.41,19.14 18.41,19.9 8.5,19.9 TV'.6
  Bottom 0.254: R9.2 25.27,12.28 28.32,12.28 R10.2
N$26  (via drill 0.61)
  Top 0.254: v123.57,13.04 123.57,16.85 122.8,17.62 122.8,22.19 IC15.12 | v108.33,12.28 105.28,9.23 105.28,5.42 106.04,4.66 109.09,4.66 109.09,6.19 SV1.13
  Bottom 0.254: v123.57,13.04 122.8,12.28 v108.33,12.28
N$27
  Top 0.254: IC15.15 115.18,22.19 111.37,18.38 111.37,11.52 109.09,9.23 SV1.14
N$28
  Top 0.254: R11.2 30.6,10.76 30.6,7.71 29.84,6.95 24.51,6.95 24.51,3.14 X3.13 24.51,2.38 22.22,4.66 21.46,3.9 20.7,3.9 19.93,4.66 18.41,4.66 6.98,16.09 6.98,19.14 6.22,19.9 TV'.4
N$29
  Bottom 0.254: IC3.14 13.84,75.53 13.84,86.19 19.93,86.19 21.46,87.72 F.2
N$30
  Top 0.254: X3.14 22.22,2.38 21.46,2.38 20.7,1.61 9.27,1.61 9.27,5.42 5.46,9.23 1.65,9.23 1.65,18.38 3.17,19.9 TV'.2
  Bottom 0.254: R12.2 34.41,11.52 33.65,10.76 9.27,10.76 3.93,16.09 2.41,16.09 1.65,16.85 1.65,19.9 3.17,19.9 TV'.2
N$32
  Top 0.254: 5V.K 77.85,54.19 77.85,58.76 R15.1
N$34
  Top 0.254: RED.A 18.41,84.67 20.7,86.96 26.03,86.96 26.03,88.48 26.79,89.24 29.08,89.24 29.84,90 34.41,90 34.41,87.72 37.46,84.67 RN2.2
N$35  (via drill 0.61)
  Top 1.27: IC7.7 51.18,56.48 48.89,58.76 48.89,59.52 D2.C 48.13,60.29 48.13,67.91 v49.65,69.43 49.65,76.29 IC10.2
  Bottom 1.27: v49.65,69.43 56.51,69.43 L2.1
N$36
  Top 0.254: IC3.1 7.74,66.38 3.17,61.81 C6.+
N$37
  Bottom 0.254: IC3.3 13.08,66.38 8.5,61.81 C6.-
N$38
  Top 0.254: IC3.4 16.12,66.38 17.65,64.86 17.65,61.81 C7.+
N$39
  Bottom 0.254: IC3.5 18.41,66.38 22.98,61.81 C7.-
N$40
  Top 0.254: IC3.2 10.79,61.81 C8.+
N$41
  Bottom 0.254: IC3.6 21.46,66.38 24.51,63.33 29.84,63.33 C10.-
N$42  (via drill 0.61)
  Top 0.254: v41.27,57.24 41.27,55.71 45.84,51.14 R16.1
  Bottom 0.254: v41.27,57.24 38.98,59.52 LED1.K
N$43
  Bottom 0.254: GRN.A 26.79,84.67 27.55,85.43 38.98,85.43 39.75,84.67 RN2.3
N$44
  Bottom 0.254: RN2.4 42.79,84.67 43.56,85.43 50.41,85.43 51.18,84.67 RED..A
N$45
  Bottom 0.254: RN2.5 45.08,83.15 58.03,83.15 58.8,83.91 GRN..A
N$46
  Top 0.254: U$1.8 64.13,29.05 64.13,28.28 67.18,25.24 69.46,25.24 69.46,32.09 RN1.6
N$49
  Top 0.254: M.1 62.61,88.48 61.84,89.24 61.84,90 M.6
  Bottom 0.254: M.4 54.99,88.48 55.75,89.24 61.08,89.24 61.84,90 M.6
N$51
  Top 0.254: M.8 56.51,90.77 58.8,90.77 M.7
N$57
  Bottom 0.254: IC3.7 23.74,66.38 25.27,64.86 42.79,64.86 43.56,65.62 44.32,65.62 46.6,63.33 58.03,63.33 66.42,71.72 66.42,76.29 62.61,80.1 62.61,86.96 58.8,86.96 58.03,87.72 M.3
N$61
  Top 0.254: IC3.8 26.03,67.91 29.08,70.95 29.08,77.81 31.36,80.1 31.36,81.62 50.41,81.62 50.41,88.48 51.18,89.24 60.32,89.24 60.32,88.48 M.2
P8  (via drill 0.61)
  Top 0.762: v34.41,35.9 34.41,30.57 33.65,29.81 IC6.13 | IC4.4 RN1.4
  Bottom 0.762: v34.41,35.9 38.22,39.71 61.84,39.71 64.13,37.43 IC4.4
P9  (via drill 0.61)
  Top 0.254: v35.94,35.14 35.94,29.81 IC6.14
  Bottom 0.254: v35.94,35.14 53.46,35.14 54.22,35.9 56.51,35.9 IC4.1
P10  (via drill 0.61)
  Top 0.254: v38.98,38.19 38.98,29.81 IC6.15
  Bottom 0.254: v38.98,38.19 39.75,38.95 57.27,38.95 58.8,37.43 IC4.2
P11  (via drill 0.61)
  Top 0.254: v54.22,37.43 58.03,41.24 61.08,41.24 61.08,37.43 IC4.3 | IC6.16 v41.27,36.66
  Bottom 0.254: v41.27,36.66 42.03,37.43 v54.22,37.43
P12  (via drill 0.61)
  Top 0.254: v67.94,26.76 65.65,29.05 U$1.7 | v71.75,26.76 RN1.7 | v45.84,25.24 45.84,26.76 44.32,28.28 IC6.17
  Bottom 0.254: v71.75,26.76 v67.94,26.76 67.18,26 46.6,26 v45.84,25.24
P13  (via drill 0.61)
  Top 0.254: U$1.5 70.23,29.05 70.23,26.76 v71.75,25.24 74.8,25.24 74.8,27.52 74.04,28.28 74.04,32.09 RN1.8 | v48.89,24.47 48.89,26 46.6,28.28 IC6.18
  Bottom 0.254: v48.89,24.47 49.65,25.24 v71.75,25.24
P14  (via drill 0.61)
  Top 0.254: v78.61,26.76 78.61,29.05 U$1.2 | v86.99,26.76 90.8,30.57 v90.8,42.76 | IC6.19 v48.89,41.24
  Bottom 0.254: v86.99,26.76 v78.61,26.76 | v90.8,42.76 90.04,43.52 82.42,43.52 77.85,38.95 74.04,38.95 73.27,38.19 73.27,30.57 | 73.27,30.57 74.8,30.57 76.32,32.09 RN1.9 | v48.89,41.24 49.65,40.47 62.61,40.47 65.65,37.43 65.65,30.57 73.27,30.57
P15
  Top 0.254: 80.13,29.05 79.37,29.81 RN1.10 | 80.13,29.05 80.13,8.47 62.61,8.47 59.56,11.52 59.56,20.66 51.94,28.28 IC6.20 | 80.13,29.05 U$1.1
P16  (via drill 0.61)
  Top 0.254: v45.84,19.9 50.41,24.47 50.41,42.76 51.18,43.52 IC6.21
  Bottom 0.254: v45.84,19.9 36.7,19.9 35.17,21.43 R12.1
P17  (via drill 0.61)
  Top 0.254: v32.13,35.9 32.13,22.19 R11.1
  Bottom 0.254: v32.13,35.9 38.22,42 47.37,42 48.89,43.52 IC6.22
P18
  Top 0.254: R10.1 28.32,21.43 29.08,20.66 29.08,19.9 30.6,18.38 35.94,18.38 35.94,26 37.46,27.52 37.46,45.81 38.98,47.33 45.84,47.33 45.84,45.05 IC6.23
P19
  Top 0.254: R9.1 25.27,21.43 29.84,16.85 38.98,16.85 38.98,26.76 39.75,27.52 39.75,37.43 40.51,38.19 40.51,42.76 39.75,43.52 39.75,45.05 41.27,46.57 43.56,46.57 43.56,45.05 IC6.24
P20
  Top 0.254: R8.1 22.22,21.43 24.51,21.43 29.84,16.09 42.79,16.09 42.79,42 41.27,43.52 IC6.25
P21  (via drill 0.61)
  Top 0.254: v22.22,35.14 22.22,25.24 R7.1
  Bottom 0.254: v22.22,35.14 24.51,37.43 32.13,37.43 38.22,43.52 IC6.26
P22  (via drill 0.61)
  Top 0.254: v14.6,32.09 14.6,22.95 15.36,22.19 R6.1
  Bottom 0.254: v14.6,32.09 21.46,38.95 31.36,38.95 35.94,43.52 IC6.27
P23  (via drill 0.61)
  Top 0.254: v12.31,33.62 12.31,22.19 R5.1
  Bottom 0.254: v12.31,33.62 20.7,42 32.13,42 33.65,43.52 IC6.28
P24  (via drill 0.61)
  Top 0.254: IC6.33 21.46,45.05 21.46,64.86 22.22,65.62 22.22,72.48 22.98,73.24 22.98,74 IC3.10 | v35.17,80.1 49.65,80.1 53.46,83.91 RED..K
  Bottom 0.254: v35.17,80.1 33.65,81.62 22.98,81.62 22.22,80.86 22.22,75.53 22.98,75.53 IC3.10
P25  (via drill 0.61)
  Top 0.254: v35.94,48.09 37.46,49.62 37.46,64.1 42.03,68.67 42.03,76.29 R2.2
  Bottom 0.254: v35.94,48.09 21.46,48.09 18.41,45.05 IC6.34
P26  (via drill 0.61)
  Top 0.254: v19.93,24.47 19.93,29.81 19.17,30.57 19.17,40.47 16.12,43.52 IC6.35
  Bottom 0.254: v19.93,24.47 20.7,23.71 38.22,23.71 39.75,22.19 R4.1
P27  (via drill 0.61)
  Top 0.254: v37.46,21.43 37.46,17.62 30.6,17.62 28.32,19.9 28.32,20.66 24.51,24.47 24.51,34.38 19.93,38.95 19.93,46.57 15.36,46.57 13.84,45.05 IC6.36
  Bottom 0.254: v37.46,21.43 38.22,20.66 42.79,20.66 43.56,21.43 R3.1
P28
  Top 0.254: IC6.37 10.79,43.52 9.27,42 6.98,42 6.98,54.19 7.74,54.95 IC1.6
P29  (via drill 0.61)
  Top 0.254: IC6.38 8.5,45.05 9.27,45.81 9.27,53.43 10.79,54.95 IC1.5 | v61.08,54.19 61.08,51.91 65.65,47.33 65.65,34.38 66.42,33.62 RN1.5
  Bottom 0.254: v61.08,54.19 57.27,58 43.56,58 41.27,55.71 IC1.5
P30
  Top 0.254: 19.93,72.48 20.7,72.48 20.7,74 IC3.11 | 19.93,72.48 13.84,72.48 9.27,67.91 9.27,65.62 4.69,61.05 4.69,45.81 5.46,45.05 IC6.39 | 19.93,72.48 19.93,83.15 20.7,83.91 RED.K
P31  (via drill 0.61)
  Top 0.254: v32.89,51.91 33.65,52.67 33.65,61.05 36.7,64.1 36.7,74.77 38.22,76.29 R1.2
  Bottom 0.254: v32.89,51.91 1.65,51.91 1.65,46.57 3.17,45.05 IC6.40

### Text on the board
tNames: Male | Female | Female | Male | Female | Male | 5V | 3V3 | See note in SD card area | See note in SD card area | These two caps on underside of board | Propeller Dracblade v5 Feb 2010 | SD card | Install LM2575 or 7805 or LM1117-5V | Install one of three 3V regulators | VGA | Keyboard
